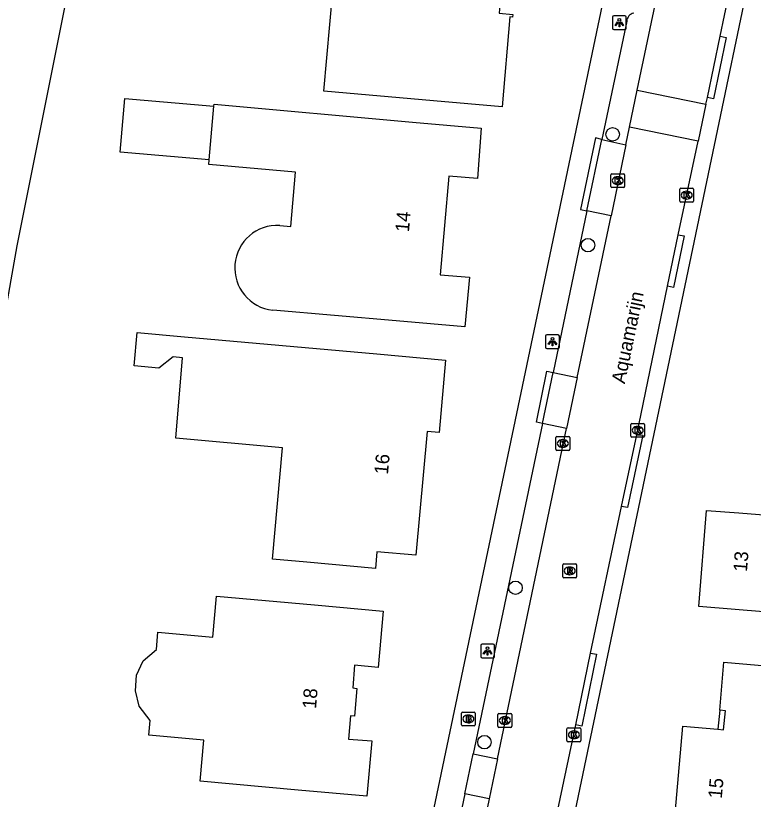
# Model space of a CAD drawing. Extents: x 159628 to 160723, y 388176 to 389416.
# Drawn here: x 159856.8 to 159910.3, y 388534.9 to 388591.8 of the extents above; entities that cross this region are included whole.
import ezdxf

# ---------------------------------------------------------------- set-up
doc = ezdxf.new("R2010")
doc.units = 0
for name, color, linetype in [('IMGEO_Boom', 7, 'Continuous'), ('IMGEO_Brandkraan', 7, 'Continuous'), ('IMGEO_Groenvoorziening', 7, 'Continuous'), ('IMGEO_Kolk', 7, 'Continuous'), ('IMGEO_Lichtpunt', 7, 'Continuous'), ('IMGEO_Openbare_ruimte_label', 7, 'Continuous'), ('IMGEO_Pand', 7, 'Continuous'), ('IMGEO_Pand_nummerreeks', 7, 'Continuous'), ('IMGEO_Pand_overbouw', 7, 'Continuous'), ('IMGEO_Parkeervlak_open', 7, 'Continuous'), ('IMGEO_Rijbaan_lokaal_open', 7, 'Continuous'), ('IMGEO_Rioolput', 7, 'Continuous'), ('IMGEO_Voetpad_open', 7, 'Continuous')]:
    doc.layers.add(name, color=color, linetype=linetype)

msp = doc.modelspace()

# ---------------------------------------------------------------- linework, layer by layer
at = {"layer": 'IMGEO_Boom'}
for centre in [(159900.068, 388583.165), (159898.281, 388575.119), (159893.023, 388550.261), (159890.77, 388539.059)]:
    msp.add_circle(centre, 0.489, dxfattribs=at)
at = {"layer": 'IMGEO_Brandkraan'}
for p, q in [((159889.18, 388541.244), (159890.032, 388541.244)), ((159889.105, 388540.318), (159889.105, 388541.17)), ((159889.593, 388541.024), (159889.618, 388541.024)), ((159890.106, 388541.17), (159890.106, 388540.318)), ((159890.032, 388540.244), (159889.18, 388540.244)), ((159889.616, 388540.464), (159889.591, 388540.464))]:
    msp.add_line(p, q, dxfattribs=at)
for points in [[(159889.18, 388541.244), (159890.032, 388541.244)], [(159889.105, 388540.318), (159889.105, 388541.17)], [(159889.453, 388540.944), (159889.453, 388540.544), (159889.666, 388540.544)], [(159889.684, 388540.944), (159889.453, 388540.944)], [(159889.632, 388540.863), (159889.578, 388540.863), (159889.578, 388540.787)], [(159889.578, 388540.787), (159889.631, 388540.787)], [(159889.64, 388540.711), (159889.578, 388540.711), (159889.578, 388540.63)], [(159890.106, 388541.17), (159890.106, 388540.318)], [(159890.032, 388540.244), (159889.18, 388540.244)], [(159889.578, 388540.63), (159889.64, 388540.63)]]:
    msp.add_lwpolyline(points, dxfattribs=at)
for centre, radius, start, end in [((159889.182, 388541.168), 0.0765, 91.552, 178.448), ((159889.182, 388541.168), 0.0765, 91.552, 178.448), ((159890.03, 388541.168), 0.0765, 1.552, 88.448), ((159890.03, 388541.168), 0.0765, 1.552, 88.448), ((159889.633, 388540.825), 0.0379, 267.8285, 90.9355), ((159889.641, 388540.67), 0.0404, 269.8759, 90.5077), ((159889.688, 388540.799), 0.145, 59.4692, 91.5367), ((159889.713, 388540.846), 0.0922, 285.5137, 58.1501), ((159889.718, 388540.654), 0.105, 301.3115, 78.989), ((159889.182, 388540.32), 0.0765, 181.552, 268.448), ((159889.182, 388540.32), 0.0765, 181.552, 268.448), ((159889.672, 388540.795), 0.251, 268.6676, 293.5347), ((159890.03, 388540.32), 0.0765, 271.552, 358.448), ((159890.03, 388540.32), 0.0765, 271.552, 358.448)]:
    msp.add_arc(centre, radius, start, end, dxfattribs=at)
for centre, major_axis, ratio, start_param, end_param in [((159889.592, 388540.744), (-0.387, 0.002), 0.722429, 4.712389, 7.853982), ((159889.617, 388540.744), (-0.39, 0.002), 0.717154, 1.570796, 4.712389)]:
    msp.add_ellipse(centre, major_axis=major_axis, ratio=ratio, start_param=start_param, end_param=end_param, dxfattribs=at)
at = {"layer": 'IMGEO_Groenvoorziening'}
msp.add_lwpolyline([(159903.537, 388612.665), (159870.877, 388640.759), (159868.257, 388629.83), (159864.584, 388613.795), (159856.856, 388575.073), (159855.899, 388569.574), (159854.79, 388569.739), (159851.654, 388551.438), (159850.278, 388539.543), (159849.747, 388535.829), (159848.144, 388535.96), (159846.739, 388520.388), (159844.261, 388504.071), (159845.431, 388503.898), (159845.39, 388503.573), (159844.145, 388501.837), (159842.914, 388499.536), (159840.587, 388493.046), (159838.043, 388487.206), (159836.317, 388482.533), (159835.337, 388480.671), (159834.576, 388478.554), (159834.22, 388476.551)], dxfattribs=at)
at = {"layer": 'IMGEO_Kolk'}
for p, q in [((159899.938, 388579.376), (159899.938, 388580.228)), ((159900.013, 388580.302), (159900.865, 388580.302)), ((159900.426, 388580.082), (159900.451, 388580.082)), ((159900.939, 388580.228), (159900.939, 388579.376)), ((159900.449, 388579.522), (159900.424, 388579.522)), ((159900.865, 388579.302), (159900.013, 388579.302)), ((159904.942, 388578.323), (159904.942, 388579.175)), ((159905.017, 388579.249), (159905.869, 388579.249)), ((159905.43, 388579.029), (159905.455, 388579.029)), ((159905.943, 388579.175), (159905.943, 388578.323)), ((159905.869, 388578.249), (159905.017, 388578.249)), ((159905.453, 388578.469), (159905.428, 388578.469)), ((159901.388, 388561.26), (159901.388, 388562.112)), ((159901.463, 388562.186), (159902.315, 388562.186)), ((159901.876, 388561.966), (159901.901, 388561.966)), ((159902.389, 388562.112), (159902.389, 388561.26)), ((159895.955, 388560.307), (159895.955, 388561.159)), ((159896.03, 388561.233), (159896.882, 388561.233)), ((159896.956, 388561.159), (159896.956, 388560.307)), ((159902.315, 388561.186), (159901.463, 388561.186)), ((159901.899, 388561.406), (159901.874, 388561.406)), ((159896.443, 388561.013), (159896.468, 388561.013)), ((159896.882, 388560.233), (159896.03, 388560.233)), ((159896.466, 388560.453), (159896.441, 388560.453)), ((159891.751, 388540.209), (159891.751, 388541.061)), ((159891.826, 388541.135), (159892.678, 388541.135)), ((159892.239, 388540.915), (159892.264, 388540.915)), ((159892.752, 388541.061), (159892.752, 388540.209)), ((159892.678, 388540.135), (159891.826, 388540.135)), ((159892.262, 388540.355), (159892.237, 388540.355)), ((159896.758, 388539.169), (159896.758, 388540.021)), ((159896.833, 388540.095), (159897.685, 388540.095)), ((159897.246, 388539.875), (159897.271, 388539.875)), ((159897.759, 388540.021), (159897.759, 388539.169)), ((159897.685, 388539.095), (159896.833, 388539.095)), ((159897.269, 388539.315), (159897.244, 388539.315))]:
    msp.add_line(p, q, dxfattribs=at)
for points in [[(159899.938, 388579.376), (159899.938, 388580.228)], [(159900.013, 388580.302), (159900.865, 388580.302)], [(159900.259, 388580.002), (159900.382, 388580.002), (159900.382, 388579.851), (159900.512, 388580.002), (159900.676, 388580.002), (159900.53, 388579.851), (159900.683, 388579.602), (159900.531, 388579.602), (159900.446, 388579.766), (159900.382, 388579.699), (159900.382, 388579.602), (159900.259, 388579.602), (159900.259, 388580.002)], [(159900.939, 388580.228), (159900.939, 388579.376)], [(159900.865, 388579.302), (159900.013, 388579.302)], [(159904.942, 388578.323), (159904.942, 388579.175)], [(159905.017, 388579.249), (159905.869, 388579.249)], [(159905.263, 388578.949), (159905.386, 388578.949), (159905.386, 388578.798), (159905.516, 388578.949), (159905.68, 388578.949), (159905.534, 388578.798), (159905.687, 388578.549), (159905.535, 388578.549), (159905.45, 388578.713), (159905.386, 388578.646), (159905.386, 388578.549), (159905.263, 388578.549), (159905.263, 388578.949)], [(159905.943, 388579.175), (159905.943, 388578.323)], [(159905.869, 388578.249), (159905.017, 388578.249)], [(159901.388, 388561.26), (159901.388, 388562.112)], [(159901.463, 388562.186), (159902.315, 388562.186)], [(159901.709, 388561.886), (159901.832, 388561.886), (159901.832, 388561.735), (159901.962, 388561.886), (159902.126, 388561.886), (159901.98, 388561.735), (159902.133, 388561.486), (159901.981, 388561.486), (159901.896, 388561.65), (159901.832, 388561.583), (159901.832, 388561.486), (159901.709, 388561.486), (159901.709, 388561.886)], [(159902.389, 388562.112), (159902.389, 388561.26)], [(159895.955, 388560.307), (159895.955, 388561.159)], [(159896.03, 388561.233), (159896.882, 388561.233)], [(159896.956, 388561.159), (159896.956, 388560.307)], [(159902.315, 388561.186), (159901.463, 388561.186)], [(159896.276, 388560.933), (159896.399, 388560.933), (159896.399, 388560.782), (159896.529, 388560.933), (159896.693, 388560.933), (159896.547, 388560.782), (159896.7, 388560.533), (159896.548, 388560.533), (159896.463, 388560.697), (159896.399, 388560.63), (159896.399, 388560.533), (159896.276, 388560.533), (159896.276, 388560.933)], [(159896.882, 388560.233), (159896.03, 388560.233)], [(159891.751, 388540.209), (159891.751, 388541.061)], [(159891.826, 388541.135), (159892.678, 388541.135)], [(159892.072, 388540.835), (159892.195, 388540.835), (159892.195, 388540.684), (159892.325, 388540.835), (159892.489, 388540.835), (159892.343, 388540.684), (159892.496, 388540.435), (159892.344, 388540.435), (159892.259, 388540.599), (159892.195, 388540.532), (159892.195, 388540.435), (159892.072, 388540.435), (159892.072, 388540.835)], [(159892.752, 388541.061), (159892.752, 388540.209)], [(159892.678, 388540.135), (159891.826, 388540.135)], [(159896.758, 388539.169), (159896.758, 388540.021)], [(159896.833, 388540.095), (159897.685, 388540.095)], [(159897.079, 388539.795), (159897.202, 388539.795), (159897.202, 388539.644), (159897.332, 388539.795), (159897.496, 388539.795), (159897.35, 388539.644), (159897.503, 388539.395), (159897.351, 388539.395), (159897.266, 388539.559), (159897.202, 388539.492), (159897.202, 388539.395), (159897.079, 388539.395), (159897.079, 388539.795)], [(159897.759, 388540.021), (159897.759, 388539.169)], [(159897.685, 388539.095), (159896.833, 388539.095)]]:
    msp.add_lwpolyline(points, dxfattribs=at)
for centre, start, end in [((159900.015, 388580.226), 91.552, 178.448), ((159900.015, 388580.226), 91.552, 178.448), ((159900.863, 388580.226), 1.552, 88.448), ((159900.863, 388580.226), 1.552, 88.448), ((159900.015, 388579.378), 181.552, 268.448), ((159900.015, 388579.378), 181.552, 268.448), ((159900.863, 388579.378), 271.552, 358.448), ((159900.863, 388579.378), 271.552, 358.448), ((159905.019, 388579.173), 91.552, 178.448), ((159905.019, 388579.173), 91.552, 178.448), ((159905.867, 388579.173), 1.552, 88.448), ((159905.867, 388579.173), 1.552, 88.448), ((159905.019, 388578.325), 181.552, 268.448), ((159905.019, 388578.325), 181.552, 268.448), ((159905.867, 388578.325), 271.552, 358.448), ((159905.867, 388578.325), 271.552, 358.448), ((159901.465, 388562.11), 91.552, 178.448), ((159901.465, 388562.11), 91.552, 178.448), ((159902.313, 388562.11), 1.552, 88.448), ((159902.313, 388562.11), 1.552, 88.448), ((159896.032, 388561.157), 91.552, 178.448), ((159896.032, 388561.157), 91.552, 178.448), ((159896.88, 388561.157), 1.552, 88.448), ((159896.88, 388561.157), 1.552, 88.448), ((159901.465, 388561.262), 181.552, 268.448), ((159901.465, 388561.262), 181.552, 268.448), ((159902.313, 388561.262), 271.552, 358.448), ((159902.313, 388561.262), 271.552, 358.448), ((159896.032, 388560.309), 181.552, 268.448), ((159896.032, 388560.309), 181.552, 268.448), ((159896.88, 388560.309), 271.552, 358.448), ((159896.88, 388560.309), 271.552, 358.448), ((159891.828, 388541.059), 91.552, 178.448), ((159891.828, 388541.059), 91.552, 178.448), ((159892.676, 388541.059), 1.552, 88.448), ((159892.676, 388541.059), 1.552, 88.448), ((159891.828, 388540.211), 181.552, 268.448), ((159891.828, 388540.211), 181.552, 268.448), ((159892.676, 388540.211), 271.552, 358.448), ((159892.676, 388540.211), 271.552, 358.448), ((159896.835, 388540.019), 91.552, 178.448), ((159896.835, 388540.019), 91.552, 178.448), ((159897.683, 388540.019), 1.552, 88.448), ((159897.683, 388540.019), 1.552, 88.448), ((159896.835, 388539.171), 181.552, 268.448), ((159896.835, 388539.171), 181.552, 268.448), ((159897.683, 388539.171), 271.552, 358.448), ((159897.683, 388539.171), 271.552, 358.448)]:
    msp.add_arc(centre, 0.0765, start, end, dxfattribs=at)
for centre, major_axis, ratio, start_param, end_param in [((159900.425, 388579.802), (-0.387, 0.002), 0.722429, 4.712389, 7.853982), ((159900.45, 388579.802), (-0.39, 0.002), 0.717154, 1.570796, 4.712389), ((159905.429, 388578.749), (-0.387, 0.002), 0.722429, 4.712389, 7.853982), ((159905.454, 388578.749), (-0.39, 0.002), 0.717154, 1.570796, 4.712389), ((159901.875, 388561.686), (-0.387, 0.002), 0.722429, 4.712389, 7.853982), ((159901.9, 388561.686), (-0.39, 0.002), 0.717154, 1.570796, 4.712389), ((159896.442, 388560.733), (-0.387, 0.002), 0.722429, 4.712389, 7.853982), ((159896.467, 388560.733), (-0.39, 0.002), 0.717154, 1.570796, 4.712389), ((159892.238, 388540.635), (-0.387, 0.002), 0.722429, 4.712389, 7.853982), ((159892.263, 388540.635), (-0.39, 0.002), 0.717154, 1.570796, 4.712389), ((159897.245, 388539.595), (-0.387, 0.002), 0.722429, 4.712389, 7.853982), ((159897.27, 388539.595), (-0.39, 0.002), 0.717154, 1.570796, 4.712389)]:
    msp.add_ellipse(centre, major_axis=major_axis, ratio=ratio, start_param=start_param, end_param=end_param, dxfattribs=at)
at = {"layer": 'IMGEO_Lichtpunt'}
for p, q in [((159900.056, 388591.667), (159900.056, 388590.86)), ((159900.056, 388591.667), (159900.056, 388590.86)), ((159900.958, 388591.762), (159900.15, 388591.762)), ((159900.958, 388591.762), (159900.15, 388591.762)), ((159901.052, 388590.86), (159901.052, 388591.667)), ((159901.052, 388590.86), (159901.052, 388591.667)), ((159900.15, 388590.766), (159900.958, 388590.766)), ((159900.15, 388590.766), (159900.958, 388590.766)), ((159895.208, 388568.528), (159895.208, 388567.721)), ((159895.208, 388568.528), (159895.208, 388567.721)), ((159896.11, 388568.623), (159895.302, 388568.623)), ((159896.11, 388568.623), (159895.302, 388568.623)), ((159896.204, 388567.721), (159896.204, 388568.528)), ((159896.204, 388567.721), (159896.204, 388568.528)), ((159895.302, 388567.627), (159896.11, 388567.627)), ((159895.302, 388567.627), (159896.11, 388567.627)), ((159890.503, 388546.074), (159890.503, 388545.267)), ((159890.503, 388546.074), (159890.503, 388545.267)), ((159891.405, 388546.169), (159890.597, 388546.169)), ((159891.405, 388546.169), (159890.597, 388546.169)), ((159891.499, 388545.267), (159891.499, 388546.074)), ((159891.499, 388545.267), (159891.499, 388546.074)), ((159890.597, 388545.173), (159891.405, 388545.173)), ((159890.597, 388545.173), (159891.405, 388545.173))]:
    msp.add_line(p, q, dxfattribs=at)
for points in [[(159900.43, 388591.331), (159900.469, 388591.303), (159900.281, 388591.041), (159900.243, 388591.068), (159900.43, 388591.331)], [(159900.532, 388591.283), (159900.579, 388591.283), (159900.579, 388590.961), (159900.532, 388590.961), (159900.532, 388591.283)], [(159900.642, 388591.303), (159900.68, 388591.33), (159900.867, 388591.068), (159900.828, 388591.04), (159900.642, 388591.303)], [(159895.582, 388568.192), (159895.621, 388568.164), (159895.433, 388567.902), (159895.395, 388567.929), (159895.582, 388568.192)], [(159895.684, 388568.144), (159895.731, 388568.144), (159895.731, 388567.822), (159895.684, 388567.822), (159895.684, 388568.144)], [(159895.794, 388568.164), (159895.832, 388568.191), (159896.019, 388567.929), (159895.98, 388567.901), (159895.794, 388568.164)], [(159890.877, 388545.738), (159890.916, 388545.71), (159890.728, 388545.448), (159890.69, 388545.475), (159890.877, 388545.738)], [(159890.979, 388545.69), (159891.026, 388545.69), (159891.026, 388545.368), (159890.979, 388545.368), (159890.979, 388545.69)], [(159891.089, 388545.71), (159891.127, 388545.737), (159891.314, 388545.475), (159891.275, 388545.447), (159891.089, 388545.71)]]:
    msp.add_lwpolyline(points, dxfattribs=at)
for centre in [(159900.555, 388591.465), (159895.707, 388568.326), (159891.002, 388545.872)]:
    msp.add_circle(centre, 0.0994, dxfattribs=at)
for centre, start, end in [((159900.15, 388591.667), 90, 180), ((159900.15, 388591.667), 90, 180), ((159900.958, 388591.667), 0, 90), ((159900.958, 388591.667), 0, 90), ((159900.15, 388590.86), 180, 270), ((159900.15, 388590.86), 180, 270), ((159900.958, 388590.86), 270, 0), ((159900.958, 388590.86), 270, 360), ((159895.302, 388568.528), 90, 180), ((159895.302, 388568.528), 90, 180), ((159896.11, 388568.528), 0, 90), ((159896.11, 388568.528), 0, 90), ((159895.302, 388567.721), 180, 270), ((159895.302, 388567.721), 180, 270), ((159896.11, 388567.721), 270, 0), ((159896.11, 388567.721), 270, 360), ((159890.597, 388546.074), 90, 180), ((159890.597, 388546.074), 90, 180), ((159891.405, 388546.074), 0, 90), ((159891.405, 388546.074), 0, 90), ((159890.597, 388545.267), 180, 270), ((159890.597, 388545.267), 180, 270), ((159891.405, 388545.267), 270, 0), ((159891.405, 388545.267), 270, 360)]:
    msp.add_arc(centre, 0.0946, start, end, dxfattribs=at)
at = {"layer": 'IMGEO_Pand'}
for points in [[(159872.4, 388594.22), (159873.11, 388602.22), (159890.121, 388600.728), (159895.101, 388600.291), (159894.524, 388594.006), (159893.019, 388594.19), (159892.036, 388594.311), (159891.838, 388591.95), (159892.824, 388591.867), (159892.807, 388591.667), (159892.605, 388591.683), (159892.059, 388585.15), (159887.079, 388585.59), (159879.122, 388586.294), (159879.765, 388593.569), (159872.4, 388594.22)], [(159870.808, 388581.302), (159864.354, 388581.864), (159864.694, 388585.766), (159871.148, 388585.204)], [(159870.808, 388581.302), (159871.148, 388585.204)], [(159871.148, 388585.204), (159871.16, 388585.34), (159885.557, 388584.052), (159890.537, 388583.606), (159890.274, 388579.96), (159888.18, 388580.138), (159887.557, 388572.968), (159889.688, 388572.787), (159889.353, 388569.19), (159884.372, 388569.624), (159875.415, 388570.404)], [(159875.928, 388576.55), (159876.729, 388576.48), (159877.072, 388580.416), (159870.779, 388580.965), (159870.808, 388581.302)], [(159868.39, 388561.11), (159868.882, 388566.952), (159868.194, 388567.009), (159867.157, 388566.197), (159865.365, 388566.357), (159865.581, 388568.776), (159869.01, 388568.47), (159882.96, 388567.225), (159887.94, 388566.78), (159887.496, 388561.533), (159886.609, 388561.603), (159885.79, 388552.622), (159882.972, 388552.878), (159882.862, 388551.663), (159877.883, 388552.116), (159875.394, 388552.342), (159876.127, 388560.407), (159868.39, 388561.11)], [(159916.024, 388548.09), (159911.296, 388548.483), (159906.313, 388548.897), (159906.882, 388555.88), (159909.22, 388555.697), (159913.716, 388555.325), (159914.005, 388558.593), (159918.988, 388558.169), (159920.366, 388558.052), (159919.803, 388551.28), (159916.313, 388551.57), (159916.024, 388548.09)], [(159866.44, 388539.57), (159866.532, 388540.632), (159865.735, 388541.677), (159865.459, 388542.782), (159865.528, 388543.911), (159866.029, 388544.959), (159866.98, 388545.78), (159867.09, 388547.04), (159871.065, 388546.681), (159871.335, 388549.662), (159878.438, 388549.021), (159883.417, 388548.571), (159883.069, 388544.471), (159881.353, 388544.641), (159881.233, 388543.013), (159881.528, 388542.955), (159881.344, 388540.946), (159881.057, 388540.977), (159880.9, 388539.289), (159882.609, 388539.152), (159882.252, 388535.13), (159877.273, 388535.581), (159870.148, 388536.226), (159870.418, 388539.21), (159866.44, 388539.57)], [(159919.392, 388530.616), (159915.146, 388530.983), (159915.127, 388530.761), (159909.392, 388531.257), (159904.41, 388531.688), (159905.15, 388540.223), (159907.693, 388539.993), (159908.107, 388539.946), (159908.255, 388541.343), (159907.844, 388541.376), (159908.122, 388544.871), (159913.104, 388544.44), (159916.068, 388544.184), (159915.649, 388539.34), (159915.868, 388539.321), (159920.114, 388538.954), (159919.392, 388530.616)]]:
    msp.add_lwpolyline(points, dxfattribs=at)
msp.add_arc((159875.745, 388573.471), 3.085, 86.5972, 263.8601, dxfattribs=at)
at = {"layer": 'IMGEO_Pand_overbouw'}
msp.add_lwpolyline([(159907.693, 388539.993), (159908.107, 388539.946), (159908.255, 388541.343), (159907.844, 388541.376)], close=True, dxfattribs=at)
at = {"layer": 'IMGEO_Parkeervlak_open'}
for points in [[(159899.283, 388582.799), (159901.032, 388582.402)], [(159899.954, 388577.243), (159898.198, 388577.61)], [(159895.745, 388565.885), (159897.504, 388565.517)], [(159896.73, 388561.813), (159894.97, 388562.181)], [(159889.959, 388538.221), (159891.723, 388537.852)], [(159891.115, 388534.944), (159889.351, 388535.313)]]:
    msp.add_lwpolyline(points, dxfattribs=at)
at = {"layer": 'IMGEO_Rijbaan_lokaal_open'}
for points in [[(159907.864, 388590.284), (159909.761, 388599.318)], [(159901.859, 388586.36), (159903.349, 388593.491)], [(159906.939, 388585.824), (159907.864, 388590.284)], [(159901.302, 388583.693), (159901.859, 388586.36)], [(159901.859, 388586.36), (159906.837, 388585.341)], [(159906.837, 388585.341), (159906.939, 388585.824)], [(159906.837, 388585.341), (159906.268, 388582.656)], [(159901.032, 388582.402), (159901.302, 388583.693)], [(159906.268, 388582.656), (159901.302, 388583.693)], [(159901.032, 388582.402), (159899.954, 388577.243)], [(159904.831, 388575.878), (159906.268, 388582.656)], [(159897.504, 388565.517), (159899.954, 388577.243)], [(159904.043, 388572.152), (159904.831, 388575.878)], [(159901.827, 388561.363), (159904.043, 388572.152)], [(159897.504, 388565.517), (159896.73, 388561.813)], [(159891.723, 388537.852), (159896.73, 388561.813)], [(159900.706, 388556.171), (159901.827, 388561.363)], [(159898.454, 388545.528), (159900.706, 388556.171)], [(159897.401, 388540.306), (159898.454, 388545.528)], [(159895.037, 388529.114), (159897.401, 388540.306)], [(159891.723, 388537.852), (159891.115, 388534.944)], [(159891.115, 388534.944), (159890.558, 388532.274)]]:
    msp.add_lwpolyline(points, dxfattribs=at)
at = {"layer": 'IMGEO_Rioolput'}
for p, q in [((159896.457, 388551.063), (159896.457, 388551.915)), ((159896.532, 388551.989), (159897.384, 388551.989)), ((159896.945, 388551.769), (159896.97, 388551.769)), ((159897.458, 388551.915), (159897.458, 388551.063)), ((159897.384, 388550.989), (159896.532, 388550.989)), ((159896.968, 388551.209), (159896.943, 388551.209))]:
    msp.add_line(p, q, dxfattribs=at)
for points in [[(159896.457, 388551.063), (159896.457, 388551.915)], [(159896.532, 388551.989), (159897.384, 388551.989)], [(159897.046, 388551.687), (159896.794, 388551.689), (159896.794, 388551.289)], [(159896.972, 388551.608), (159896.918, 388551.608), (159896.918, 388551.527)], [(159896.918, 388551.527), (159896.97, 388551.527)], [(159897.458, 388551.915), (159897.458, 388551.063)], [(159897.384, 388550.989), (159896.532, 388550.989)], [(159896.794, 388551.289), (159896.918, 388551.289), (159896.918, 388551.451), (159896.929, 388551.451)], [(159896.976, 388551.422), (159897.047, 388551.289), (159897.187, 388551.289), (159897.122, 388551.415)]]:
    msp.add_lwpolyline(points, dxfattribs=at)
for centre, radius, start, end in [((159896.534, 388551.913), 0.0765, 91.552, 178.448), ((159896.534, 388551.913), 0.0765, 91.552, 178.448), ((159896.954, 388551.716), 0.19, 274.7715, 282.9687), ((159896.978, 388551.512), 0.0964, 77.0061, 93.1865), ((159896.992, 388551.569), 0.0378, 276.6634, 79.6772), ((159897.045, 388551.577), 0.109, 350.3612, 89.416), ((159897.043, 388551.577), 0.112, 277.5842, 350.9817), ((159897.382, 388551.913), 0.0765, 1.552, 88.448), ((159897.382, 388551.913), 0.0765, 1.552, 88.448), ((159896.534, 388551.065), 0.0765, 181.552, 268.448), ((159896.534, 388551.065), 0.0765, 181.552, 268.448), ((159896.928, 388551.398), 0.0533, 26.0293, 88.6989), ((159897.027, 388551.362), 0.108, 29.5134, 73.7905), ((159897.382, 388551.065), 0.0765, 271.552, 358.448), ((159897.382, 388551.065), 0.0765, 271.552, 358.448)]:
    msp.add_arc(centre, radius, start, end, dxfattribs=at)
for centre, major_axis, ratio, start_param, end_param in [((159896.944, 388551.489), (-0.387, 0.002), 0.722429, 4.712389, 7.853982), ((159896.969, 388551.489), (-0.39, 0.002), 0.717154, 1.570796, 4.712389)]:
    msp.add_ellipse(centre, major_axis=major_axis, ratio=ratio, start_param=start_param, end_param=end_param, dxfattribs=at)
at = {"layer": 'IMGEO_Voetpad_open'}
for points in [[(159880.922, 388504.632), (159903.537, 388612.665)], [(159910.917, 388599.067), (159890.615, 388501.836)], [(159901.09, 388591.384), (159899.283, 388582.799)], [(159907.864, 388590.284), (159908.296, 388590.183), (159907.389, 388585.741), (159906.939, 388585.824)], [(159899.283, 388582.799), (159898.835, 388582.901), (159897.738, 388577.701), (159898.198, 388577.61)], [(159898.198, 388577.61), (159899.283, 388582.799)], [(159898.198, 388577.61), (159895.745, 388565.885)], [(159904.831, 388575.878), (159905.256, 388575.793), (159904.485, 388572.054), (159904.043, 388572.152)], [(159894.97, 388562.181), (159894.546, 388562.276), (159895.298, 388565.98), (159895.745, 388565.885)], [(159894.97, 388562.181), (159895.745, 388565.885)], [(159894.97, 388562.181), (159889.959, 388538.221)], [(159901.827, 388561.363), (159902.255, 388561.334), (159901.147, 388556.088), (159900.706, 388556.171)], [(159898.454, 388545.528), (159898.89, 388545.443), (159897.836, 388540.231), (159897.401, 388540.306)], [(159889.351, 388535.313), (159889.959, 388538.221)], [(159889.351, 388535.313), (159888.792, 388532.643)]]:
    msp.add_lwpolyline(points, dxfattribs=at)
msp.add_arc((159901.724, 388591.337), 0.635, 101.7721, 175.7573, dxfattribs=at)

# ---------------------------------------------------------------- texts
at = {"layer": 'IMGEO_Openbare_ruimte_label'}
msp.add_text('Aquamarijn', height=1, rotation=78.2294, dxfattribs=at).set_placement((159900.949, 388565.022))
at = {"layer": 'IMGEO_Pand_nummerreeks'}
for s, rotation, p in [('14', 85.0327, (159885.294, 388576.039)), ('16', 84.7895, (159883.771, 388558.45)), ('13', 85.3416, (159909.807, 388551.389)), ('18', 85.1644, (159878.554, 388541.448)), ('15', 85.0447, (159907.984, 388534.94))]:
    msp.add_text(s, height=1, rotation=rotation, dxfattribs=at).set_placement(p)

doc.saveas('drawing.dxf')
